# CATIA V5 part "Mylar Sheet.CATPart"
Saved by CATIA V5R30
Part number: Part1
Material "Mylar Sheet": density 1390 kg/m3, Young's modulus 6e+10 Pa, Poisson ratio 0.27
Bounding box of the stored display mesh (mm): x -1.888 to 401.888, y -1.888 to 401.888, z -22.044 to 0.226
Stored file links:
  D:\OneDrive\OneDrive - Carleton University\Courses\aero2001\Design Project\3D Models\Deployed\Mylar Sheet.CATPart
  C:\Program Files\Dassault Systemes\B30\win_b64\startup\materials\Catalog.CATMaterial
  C:\Program Files\Dassault Systemes\B30\win_b64\startup\materials\brown_fiber.jpg
  C:\Program Files\Dassault Systemes\B30\win_b64\startup\materials\raw_polystyren.jpg
  C:\Program Files\Dassault Systemes\B30\win_b64\startup\materials\blue_fabric_03.jpg
  C:\Program Files\Dassault Systemes\B30\win_b64\startup\materials\brown_fabric_01.jpg
  C:\Program Files\Dassault Systemes\B30\win_b64\startup\materials\brown_fabric_02.jpg
  C:\Program Files\Dassault Systemes\B30\win_b64\startup\materials\blue_fabric_02.jpg
  D:\OneDrive\OneDrive - Carleton University\Courses\aero2001\Design Project\3D Models\Deployed\CubeSat Assembly Deployed.CATProduct
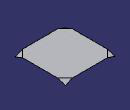
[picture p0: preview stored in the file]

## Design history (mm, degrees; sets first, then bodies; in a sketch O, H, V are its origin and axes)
Body1 (main body), material "Mylar Sheet"
  Sketch1 on xy-plane, origin (0, 0, 0), H (1, 0, 0), V (0, 1, 0)
    line L1 (60, 0) -> (340, 0)
    line L2 (400, 60) -> (400, 340)
    line L3 (340, 400) -> (60, 400)
    line L4 (0, 340) -> (0, 60)
    point P1 (400, 0)
    point P2 (400, 400)
    point P3 (0, 400)
    line L5 (340, 400) -> (400, 340)
    point P4 (340, 400)
    point P5 (400, 340)
    construction line L6 (0, 200) -> (507.1468, 200)
    point P6 (0, 200)
    axis line L7 (200, 400) -> (200, 0)
    point P8 (200, 400)
    point P9 (200, 0)
    point P10 (400, 60)
    point P11 (340, 0)
    point P12 (0, 60)
    point P13 (60, 0)
    line L8 (60, 0) -> (0, 60)
    line L9 (400, 60) -> (340, 0)
    point P14 (0, 340)
    point P15 (60, 400)
    line L10 (60, 400) -> (0, 340)
    distance P3 P2 = 400
    distance P2 P4 = 60
    distance P2 P5 = 60
    distance P3 O = 400
    horizontal: L1 H, L3 H, L6 H
    vertical: L2 V, L4 V, L7 V
    coincidence: P8 L3, L1 P9, L4 P6
    symmetry: P5 P10 L6, P4 P11 L6, P10 P12 L7, P11 P13 L7, P12 P14 L6, P13 P15 L6, L8 L10 L6
    perpendicularity: L9 L5
  Pad1: profile Sketch1, direction (0, 0, 1), length 0.12
  Point1: (0, 0, -22)
  Plane1: type 3Points, Element1 Point1, Element2 vertex [face of Pad1 from Sketch1.L8 | end face of Pad1 | face of Pad1 from Sketch1.L1], Element3 vertex [face of Pad1 from Sketch1.L8 | end face of Pad1 | face of Pad1 from Sketch1.L4]
  Sketch2 on Plane1, origin (12.7555, 12.7555, -12.595), H (0.7071, -0.7071, 0), V (0.627, 0.627, 0.4623)
    point P1 (-42.4264, 27.5031)
    line L1 (-42.4264, 27.5031) -> (42.4264, 27.5031)
    point P2 (42.4264, 27.5031)
    line L2 (42.4264, 27.5031) -> (2.5296, -20.439)
    line L3 (2.5296, -20.439) -> (-42.4264, 27.5031)
    reference projected line E1 (-42.4264, 27.5031) -> (42.4264, 27.5031) from edge [face of Pad1 from Sketch1.L8 | end face of Pad1]
    reference projected point E2 (42.4264, 27.5031) from vertex [face of Pad1 from Sketch1.L8 | end face of Pad1 | face of Pad1 from Sketch1.L1]
    reference projected point E3 (-42.4264, 27.5031) from vertex [face of Pad1 from Sketch1.L8 | end face of Pad1 | face of Pad1 from Sketch1.L4]
    horizontal: L1 H
    coincidence: E1 L1, P2 E2, P1 E3
  Pad2: profile Sketch2, direction (-0.3269, -0.3269, 0.8867), length 0.12
  Point2: type OnPlane, Support end face of Pad1, H 200, V 200, Direction (1, 0, 0)
  Line1: type Normal, RefPoint Point2, RefSkin end face of Pad1, Start 0, End 20
  CircPattern1: of Pad2, instances 4, angular step 90 {= 360.0*1 deg/CircPattern1.AngularNumber}, axis from Line1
